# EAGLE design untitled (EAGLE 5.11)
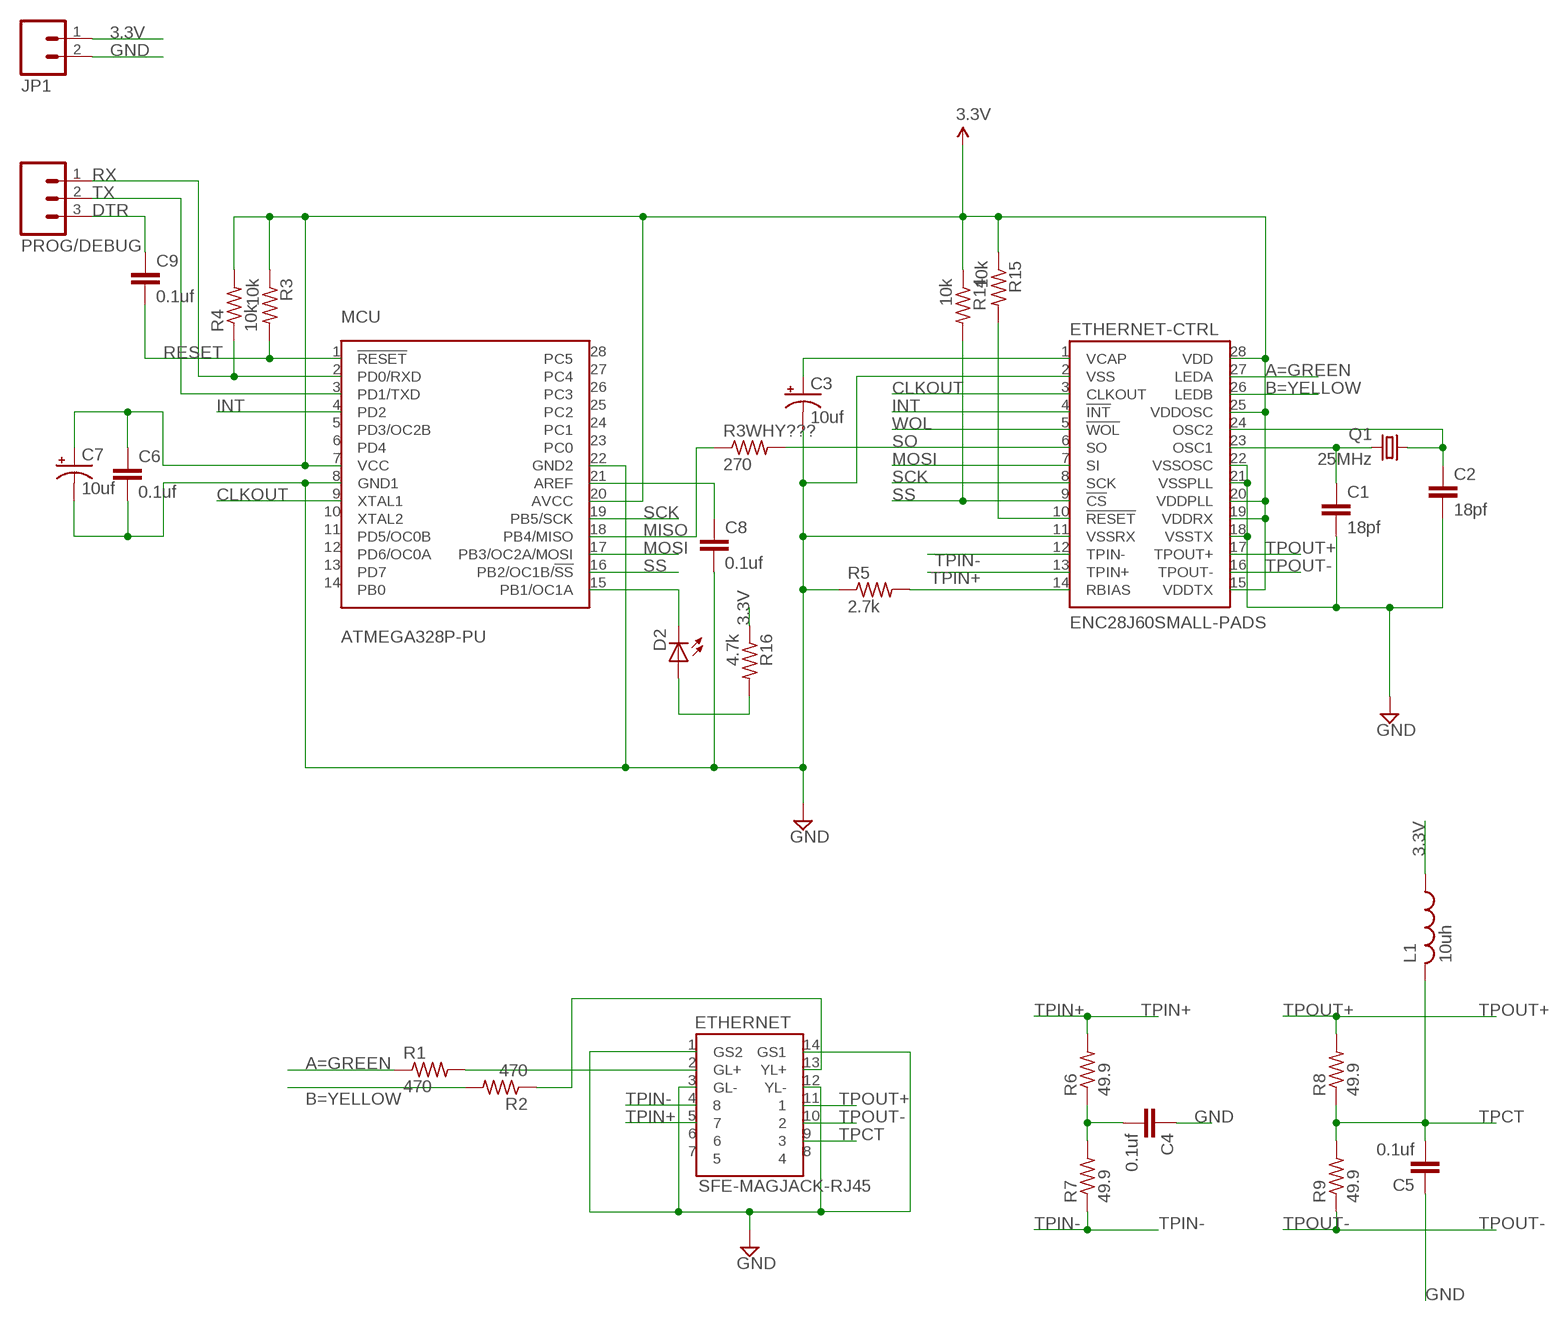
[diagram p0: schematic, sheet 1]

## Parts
C1  18pf  C-EUC0805  [C0805]
C2  18pf  C-EUC0805  [C0805]
C3  10uf  CPOL-USC  [PANASONIC_C]
C4  0.1uf  C-EUC0805  [C0805]
C5  0.1uf  C-EUC0805  [C0805]
C6  0.1uf  C-EUC0805  [C0805]
C7  10uf  CPOL-USC  [PANASONIC_C]
C8  0.1uf  C-EUC0805  [C0805]
C9  0.1uf  C-EUC0805  [C0805]
D2  LED-SMD-RED  [LED-SMD-RED]
ETHERNET  SFE-MAGJACK-RJ45  [SFE-MAGJACK-RJ45]
ETHERNET-CTRL  ENC28J60SMALL-PADS  [DIL28-3]
JP1  M02PTH  [1X02]
L1  10uh  L-USL3225M  [L3225M]
MCU  ATMEGA328P-PU  [DIL28-3]
PROG/DEBUG  M03PTH  [1X03]
Q1  25MHz  CRYSTALCTS406  [CTS406]
R1  470  R-US_R1206  [R1206]
R2  470  R-US_R1206  [R1206]
R3  10k  R-US_R0805  [R0805]
R3WHY???  270  R-US_R0805  [R0805]
R4  10k  R-US_R0805  [R0805]
R5  2.7k  R-US_R0805  [R0805]
R6  49.9  R-US_M0805  [M0805]
R7  49.9  R-US_M0805  [M0805]
R8  49.9  R-US_M0805  [M0805]
R9  49.9  R-US_M0805  [M0805]
R14  10k  R-US_R0805  [R0805]
R15  10k  R-US_R0805  [R0805]
R16  4.7k  R-US_R1206  [R1206]

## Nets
3.3V: C6.1 C7.+ ETHERNET-CTRL.15(VDDTX) ETHERNET-CTRL.19(VDDRX) ETHERNET-CTRL.20(VDDPLL) ETHERNET-CTRL.25(VDDOSC) ETHERNET-CTRL.28(VDD) JP1.1 L1.1 MCU.7(VCC) MCU.20(AVCC) R3.1 R4.2 R14.1 R15.1 R16.1
A=GREEN: ETHERNET-CTRL.27(LEDA) R1.1
B=YELLOW: ETHERNET-CTRL.26(LEDB) R2.2
CLKOUT: ETHERNET-CTRL.3(CLKOUT) MCU.9(XTAL1)
DTR: C9.1 PROG/DEBUG.3
GND: C1.2 C2.2 C3.- C4.1 C5.1 C6.2 C7.- C8.2 ETHERNET-CTRL.2(VSS) ETHERNET-CTRL.11(VSSRX) ETHERNET-CTRL.18(VSSTX) ETHERNET-CTRL.21(VSSPLL) ETHERNET-CTRL.22(VSSOSC) ETHERNET.1(GS2) ETHERNET.3(GL-) ETHERNET.12(YL-) ETHERNET.14(GS1) JP1.2 MCU.8(GND1) MCU.22(GND2) R5.1
INT: ETHERNET-CTRL.4(!INT) MCU.4(PD2)
MISO: MCU.18(PB4/MISO) R3WHY???.1
MOSI: ETHERNET-CTRL.7(SI) MCU.17(PB3/OC2A/MOSI)
N$1: C1.1 ETHERNET-CTRL.23(OSC1) Q1.3
N$2: C2.1 ETHERNET-CTRL.24(OSC2) Q1.1
N$3: C3.+ ETHERNET-CTRL.1(VCAP)
N$4: ETHERNET-CTRL.10(!RESET) R15.2
N$5: ETHERNET-CTRL.14(RBIAS) R5.2
N$6: ETHERNET.2(GL+) R1.2
N$7: D2.ANODE(A) R16.2
N$8: ETHERNET.13(YL+) R2.1
N$9: C4.2 R6.1 R7.2
N$10: D2.CATHODE(C) MCU.15(PB1/OC1A)
N$17: C8.1 MCU.21(AREF)
RESET: C9.2 MCU.1(!RESET) R3.2
RX: MCU.2(PD0/RXD) PROG/DEBUG.1 R4.1
SCK: ETHERNET-CTRL.8(SCK) MCU.19(PB5/SCK)
SO: ETHERNET-CTRL.6(SO) R3WHY???.2
SS: ETHERNET-CTRL.9(!CS) MCU.16(PB2/OC1B/!SS) R14.2
TPCT: C5.2 ETHERNET.9 L1.2 R8.1 R9.2
TPIN+: ETHERNET-CTRL.13(TPIN+) ETHERNET.5 R6.2
TPIN-: ETHERNET-CTRL.12(TPIN-) ETHERNET.4 R7.1
TPOUT+: ETHERNET-CTRL.17(TPOUT+) ETHERNET.11 R8.2
TPOUT-: ETHERNET-CTRL.16(TPOUT-) ETHERNET.10 R9.1
TX: MCU.3(PD1/TXD) PROG/DEBUG.2
WOL: ETHERNET-CTRL.5(!WOL)
Unconnected: ETHERNET.6 ETHERNET.7 ETHERNET.8 MCU.5(PD3/OC2B) MCU.6(PD4) MCU.10(XTAL2) MCU.11(PD5/OC0B) MCU.12(PD6/OC0A) MCU.13(PD7) MCU.14(PB0) MCU.23(PC0) MCU.24(PC1) MCU.25(PC2) MCU.26(PC3) MCU.27(PC4) MCU.28(PC5)

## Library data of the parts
C1 C2 C4-C6 C8 C9 = rcl:C-EU: CAPACITOR, European symbol
C3 C7 = rcl:CPOL-US: POLARIZED CAPACITOR, American symbol
D2 = trl:LED-SMD-RED
ETHERNET = trl:SFE-MAGJACK-RJ45
ETHERNET-CTRL = trl:ENC28J60
JP1 = SparkFun:M02: Header 2
L1 = rcl:L-US: INDUCTOR, American symbol
MCU = trl:ATMEGA328P-PU
PROG/DEBUG = SparkFun:M03: Header 3 Standard 3-pin 0.1" header. Use with straight break away headers (SKU : PRT-00116), right angle break away headers (PRT-00553), swiss pins (PRT-00743), machine pins (PRT-00117), and female headers (PRT-00115). Molex polarized connector foot print use with SKU : PRT-08232 with associated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
Q1 = crystal:CRYSTAL: CRYSTAL; OC_FARNELL: unknown; OC_NEWARK: unknown
R1 R2 = resistor:R-US_: RESISTOR, American symbol
R3 R3WHY??? R4-R9 R14-R16 = rcl:R-US_: RESISTOR, American symbol

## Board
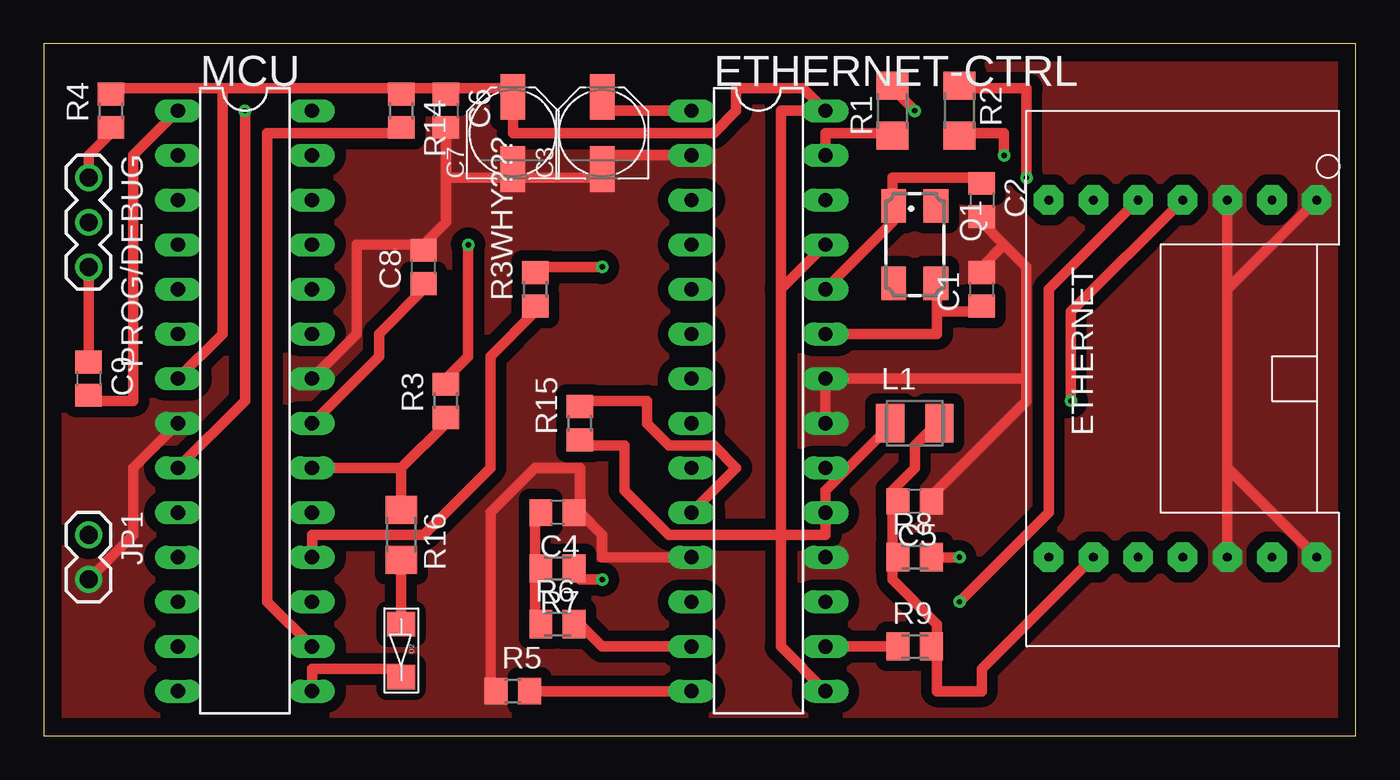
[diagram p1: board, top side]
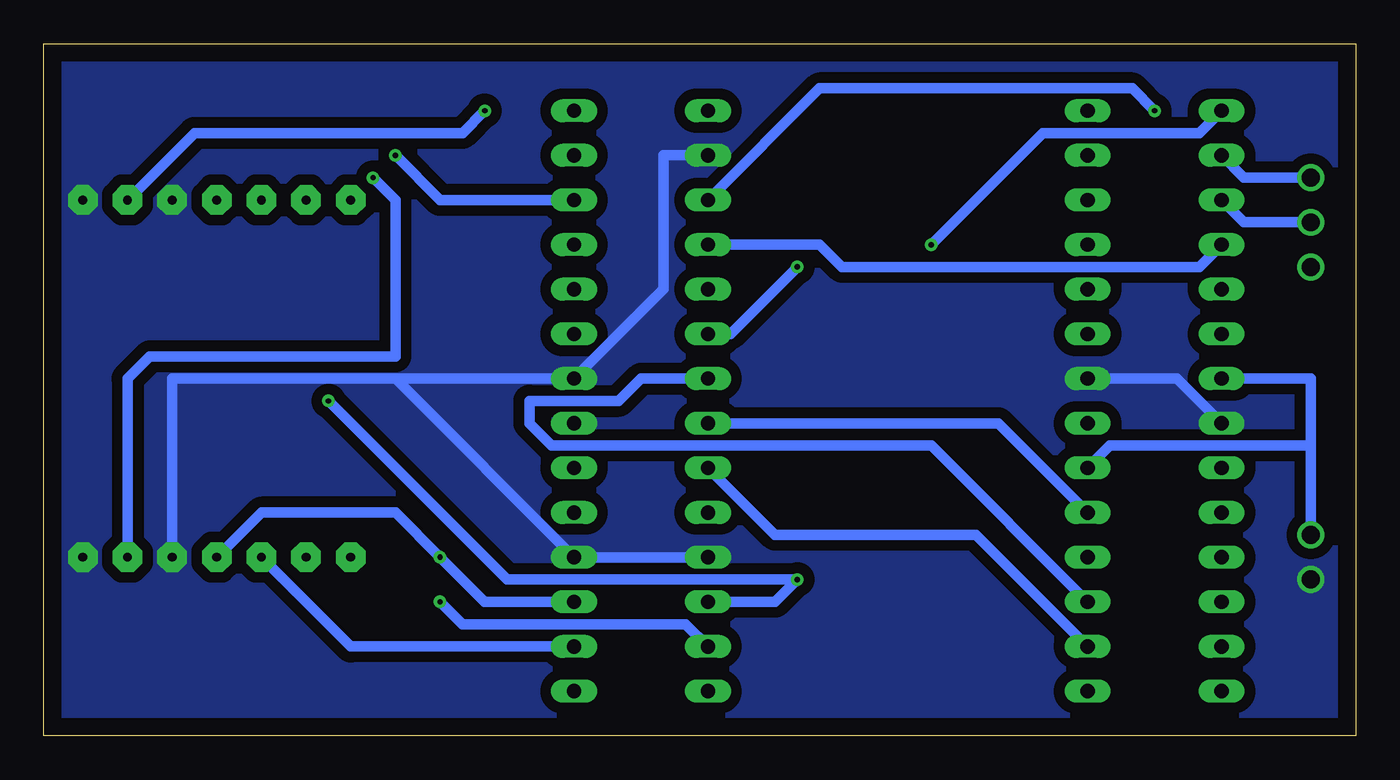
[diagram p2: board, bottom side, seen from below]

Size 74.6 x 39.36 mm. Coordinates in mm from the lower left corner, seen from the top.
Outline: 0,0 74.6,0 74.6,39.36 0,39.36 0,0
Copper layers (1*16): Top 0.035mm / dielectric 1.5mm / Bottom 0.035mm
Design rules "trl-ethernet-arduino": minimum track width 24mil, minimum drill 12mil, track to track 12mil, track to pad 12mil, pad to pad 12mil, via to via 12mil, smd to smd 12mil, copper to edge 40mil, drill to drill 12mil, minimum pad ring 10mil, minimum via ring 8mil, stop-mask expansion 4mil, vias tented up to drill 0mil, thermal gap 10mil

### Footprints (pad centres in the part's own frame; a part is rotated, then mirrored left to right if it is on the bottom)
C0805 = smd 1.3 x 1.5: 1 -0.95,0; 2 0.95,0
PANASONIC_C = smd 2.6 x 1.4: + 2.05,0; - -2.05,0
LED-SMD-RED = smd 1.4 x 1.6: ANODE 0,0; CATHODE 3,0
SFE-MAGJACK-RJ45 = drill 0.5 pad 1.676 octagon: 1 -10.16,7.62; 2 -10.16,5.08; 3 -10.16,2.54; 4 -10.16,0; 5 -10.16,-2.54; 6 -10.16,-5.08; 7 -10.16,-7.62; 8 10.16,-7.62; 9 10.16,-5.08; 10 10.16,-2.54; 11 10.16,0; 12 10.16,2.54; 13 10.16,5.08; 14 10.16,7.62
DIL28-3 = drill 0.813 long: 1 -16.51,-3.81; 2 -13.97,-3.81; 3 -11.43,-3.81; 4 -8.89,-3.81; 5 -6.35,-3.81; 6 -3.81,-3.81; 7 -1.27,-3.81; 8 1.27,-3.81; 9 3.81,-3.81; 10 6.35,-3.81; 11 8.89,-3.81; 12 11.43,-3.81; 13 13.97,-3.81; 14 16.51,-3.81; 15 16.51,3.81; 16 13.97,3.81; 17 11.43,3.81; 18 8.89,3.81; 19 6.35,3.81; 20 3.81,3.81; 21 1.27,3.81; 22 -1.27,3.81; 23 -3.81,3.81; 24 -6.35,3.81; 25 -8.89,3.81; 26 -11.43,3.81; 27 -13.97,3.81; 28 -16.51,3.81
1X02 = drill 1.016 round: 1 0,0; 2 2.54,0
L3225M = smd 1.6 x 2.2: 1 -1.4,0; 2 1.4,0
1X03 = drill 1.016 round: 1 0,0; 2 2.54,0; 3 5.08,0
CTS406 = smd 1.9 x 1.4: 1 -2.2,-1.2; 2 2.2,-1.2; 3 2.2,1.2; 4 -2.2,1.2
R1206 = smd 1.6 x 1.803: 1 -1.422,0; 2 1.422,0
R0805 = smd 1.3 x 1.5: 1 -0.95,0; 2 0.95,0
M0805 = smd 1.3 x 1.6: 1 -0.95,0; 2 0.95,0

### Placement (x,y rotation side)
C1  53.34,25.4 90 top
C2  53.34,30.48 270 top
C3  31.75,34.29 90 top
C4  29.21,12.7 180 top
C5  49.53,13.34 180 top
C6  22.86,35.56 270 top
C7  26.67,34.29 90 top
C8  21.59,26.67 90 top
C9  2.54,20.32 270 top
D2  20.32,6.35 270 top
ETHERNET  64.77,20.32 270 top
ETHERNET-CTRL  40.64,19.05 270 top
JP1  2.54,11.43 270 top
L1  49.53,17.78 0 top
MCU  11.43,19.05 270 top
PROG/DEBUG  2.54,31.75 270 top
Q1  49.53,27.94 270 top
R1  48.26,35.56 90 top
R2  52.07,35.56 270 top
R3  22.86,19.05 90 top
R3WHY???  27.94,25.4 90 top
R4  3.81,35.56 90 top
R5  26.67,2.54 0 top
R6  29.21,6.35 0 top
R7  29.21,9.53 180 top
R8  49.53,10.16 0 top
R9  49.53,5.08 0 top
R14  20.32,35.56 270 top
R15  30.48,17.78 90 top
R16  20.32,11.43 270 top

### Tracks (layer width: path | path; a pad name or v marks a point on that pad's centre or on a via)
3.3V
  Top 0.61: 41.91,11.43 44.45,11.43 ETHERNET-CTRL.19 44.45,13.97 45.72,15.24 | 41.91,11.43 35.56,11.43 33.02,13.97 33.02,16.51 30.48,16.51 R15.1 | 45.72,15.24 48.26,17.78 L1.1 | ETHERNET-CTRL.15 41.91,5.08 41.91,11.43 | 45.72,15.24 ETHERNET-CTRL.20 | 41.91,25.4 ETHERNET-CTRL.25 | 41.91,25.4 41.91,11.43 | 41.91,25.4 41.91,35.56 ETHERNET-CTRL.28 43.18,36.83 39.37,36.83 39.37,35.56 38.1,34.29 26.67,34.29 C7.+ 26.67,36.83 22.86,36.83 | 20.32,15.24 22.86,17.78 R3.1 | 20.32,15.24 R16.1 20.32,12.7 | MCU.20 20.32,15.24 | 10.16,36.83 20.32,36.83 | 10.16,36.83 3.81,36.83 R4.2 | 20.32,36.83 22.86,36.83 | 20.32,36.83 R14.1 | 22.86,36.83 C6.1 | MCU.7 10.16,22.86 10.16,36.83
  Bottom 0.61: 2.54,16.51 2.54,20.32 MCU.7 | JP1.1 2.54,16.51 | MCU.20 13.97,16.51 2.54,16.51
A=GREEN
  Top 0.61: ETHERNET-CTRL.27 44.45,34.29 48.26,34.29 R1.1
B=YELLOW  (via drill 0.3)
  Top 0.61: v54.61,33.02 54.61,34.29 52.07,34.29 R2.2
  Bottom 0.61: v54.61,33.02 52.07,30.48 ETHERNET-CTRL.26
CLKOUT  (via drill 0.3)
  Top 0.61: MCU.9 11.43,19.05 v11.43,35.56
  Bottom 0.61: v11.43,35.56 12.7,36.83 30.48,36.83 ETHERNET-CTRL.3
DTR
  Top 0.61: C9.1 PROG/DEBUG.3
GND
  Top 0.61: 30.48,12.7 30.48,15.24 27.94,15.24 25.4,12.7 25.4,2.54 R5.1 | ETHERNET-CTRL.11 31.75,10.16 31.75,11.43 30.48,12.7 | 30.48,12.7 C4.1 | 67.31,25.4 ETHERNET.3 | 67.31,15.24 67.31,25.4 | ETHERNET.12 67.31,15.24 | 67.31,15.24 ETHERNET.14 | 67.31,25.4 ETHERNET.1 | ETHERNET-CTRL.21 ETHERNET-CTRL.22 55.88,20.32 | 55.88,20.32 55.88,26.67 54.61,27.94 | 55.88,20.32 55.88,19.05 50.8,13.97 C5.1 | 54.61,27.94 53.34,29.21 C2.2 | 54.61,27.94 53.34,26.67 C1.2 | 21.59,27.94 22.86,29.21 22.86,31.75 | 22.86,31.75 C6.2 | 22.86,31.75 26.67,31.75 | 26.67,31.75 31.75,31.75 C3.- 31.75,33.02 ETHERNET-CTRL.2 | 26.67,31.75 C7.- | JP1.2 5.08,11.43 5.08,15.24 MCU.8 | 21.59,27.94 17.78,27.94 17.78,22.86 MCU.22 | 21.59,27.94 C8.2
  Bottom 0.61: ETHERNET-CTRL.11 ETHERNET-CTRL.18 54.61,20.32 | MCU.8 10.16,20.32 MCU.22 | ETHERNET-CTRL.2 39.37,33.02 39.37,25.4 ETHERNET-CTRL.22 54.61,20.32 | ETHERNET.12 67.31,20.32 54.61,20.32
  pour Top (isolate 0.61, no thermals): 0,39.37 74.93,39.37 74.93,25.4 74.93,0 0,0 0,1.27
  pour Bottom (isolate 0.61, no thermals): 0,39.37 74.93,39.37 74.93,0 0,0
INT
  Bottom 0.61: MCU.4 8.89,26.67 29.21,26.67 30.48,27.94 ETHERNET-CTRL.4
MISO
  Top 0.61: MCU.18 15.24,11.43 21.59,11.43 25.4,15.24 25.4,21.59 27.94,24.13 R3WHY???.1
MOSI
  Bottom 0.61: MCU.17 24.13,16.51 45.72,16.51 46.99,17.78 46.99,19.05 41.91,19.05 40.64,20.32 ETHERNET-CTRL.7
N$1
  Top 0.61: 50.8,24.13 53.34,24.13 C1.1 | 50.8,24.13 50.8,25.4 Q1.3 | ETHERNET-CTRL.23 50.8,22.86 50.8,24.13
N$2
  Top 0.61: C2.1 53.34,31.75 48.26,31.75 48.26,30.48 Q1.1 48.26,29.21 ETHERNET-CTRL.24
N$3
  Top 0.61: ETHERNET-CTRL.1 31.75,35.56 C3.+
N$4
  Top 0.61: ETHERNET-CTRL.10 39.37,15.24 38.1,16.51 35.56,16.51 34.29,17.78 34.29,19.05 30.48,19.05 R15.2
N$5
  Top 0.61: R5.2 ETHERNET-CTRL.14
N$6  (via drill 0.3)
  Top 0.61: v49.53,35.56 48.26,36.83 R1.2
  Bottom 0.61: v49.53,35.56 50.8,34.29 66.04,34.29 ETHERNET.2
N$7
  Top 0.61: D2.ANODE R16.2 20.32,10.16
N$8  (via drill 0.3)
  Top 0.61: v55.88,31.75 55.88,36.83 52.07,36.83 R2.1
  Bottom 0.61: v55.88,31.75 54.61,30.48 54.61,21.59 68.58,21.59 69.85,20.32 ETHERNET.13
N$9
  Top 0.61: C4.2 27.94,12.7 27.94,10.16 R7.2 27.94,8.89 27.94,6.35 R6.1
N$10
  Top 0.61: MCU.15 15.24,3.81 20.32,3.81 D2.CATHODE
N$17
  Top 0.61: MCU.21 19.05,21.59 19.05,22.86 21.59,25.4 C8.1
RESET  (via drill 0.3)
  Top 0.61: MCU.1 5.08,33.02 5.08,19.05 2.54,19.05 C9.2 | v24.13,27.94 24.13,21.59 22.86,20.32 R3.2
  Bottom 0.61: v24.13,27.94 17.78,34.29 8.89,34.29 MCU.1
RX
  Top 0.61: PROG/DEBUG.1 2.54,33.02 3.81,34.29 R4.1
  Bottom 0.61: MCU.2 6.35,31.75 PROG/DEBUG.1
SCK
  Bottom 0.61: MCU.19 20.32,17.78 ETHERNET-CTRL.8
SO  (via drill 0.3)
  Top 0.61: v31.75,26.67 27.94,26.67 R3WHY???.2
  Bottom 0.61: v31.75,26.67 35.56,22.86 ETHERNET-CTRL.6
SS
  Top 0.61: MCU.16 12.7,7.62 12.7,34.29 20.32,34.29 R14.2
  Bottom 0.61: ETHERNET-CTRL.9 33.02,11.43 21.59,11.43 MCU.16
TPCT
  Top 0.61: 48.26,10.16 48.26,12.7 C5.2 48.26,13.97 49.53,15.24 49.53,16.51 50.8,17.78 L1.2 | 50.8,5.08 50.8,6.35 48.26,8.89 48.26,10.16 | 48.26,10.16 R8.1 | ETHERNET.9 53.34,3.81 53.34,2.54 50.8,2.54 50.8,5.08 | R9.2 50.8,5.08
TPIN+  (via drill 0.3)
  Top 0.61: ETHERNET-CTRL.13 31.75,5.08 30.48,6.35 R6.2 | ETHERNET.5 57.15,25.4 57.15,12.7 v52.07,7.62
  Bottom 0.61: v52.07,7.62 50.8,6.35 38.1,6.35 ETHERNET-CTRL.13
TPIN-  (via drill 0.3)
  Top 0.61: v31.75,8.89 30.48,8.89 R7.1 | ETHERNET.4 58.42,24.13 v58.42,19.05
  Bottom 0.61: ETHERNET-CTRL.12 33.02,7.62 v31.75,8.89 48.26,8.89 v58.42,19.05
TPOUT+  (via drill 0.3)
  Top 0.61: v52.07,10.16 R8.2
  Bottom 0.61: ETHERNET-CTRL.17 49.53,7.62 v52.07,10.16 54.61,12.7 62.23,12.7 ETHERNET.11
TPOUT-
  Top 0.61: ETHERNET-CTRL.16 R9.1
  Bottom 0.61: ETHERNET.10 57.15,5.08 ETHERNET-CTRL.16
TX
  Bottom 0.61: MCU.3 6.35,29.21 PROG/DEBUG.2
